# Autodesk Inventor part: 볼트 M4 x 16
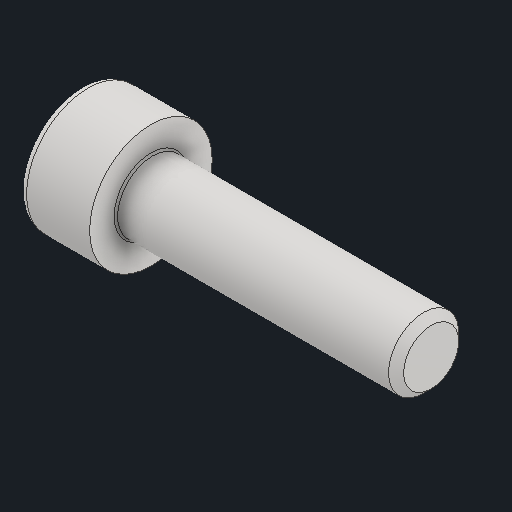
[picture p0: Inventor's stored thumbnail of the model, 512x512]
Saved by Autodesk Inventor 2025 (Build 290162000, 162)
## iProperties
Created: 2025-08
Part Number: 볼트 M4 x 16
Material: 스테인리스강
Description: 6각 소켓 머리 캡 나사
Document SubType Name: Modeling
Designer: infra15
Density: 8.08 g/cm^3
Appearance: 기본값
Author: jhkim
Sending System: Autodesk Inventor 2026
Preprocessor: ST-DEVELOPER v20.1
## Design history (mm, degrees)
feature "Solid1"
node "솔리드1"
